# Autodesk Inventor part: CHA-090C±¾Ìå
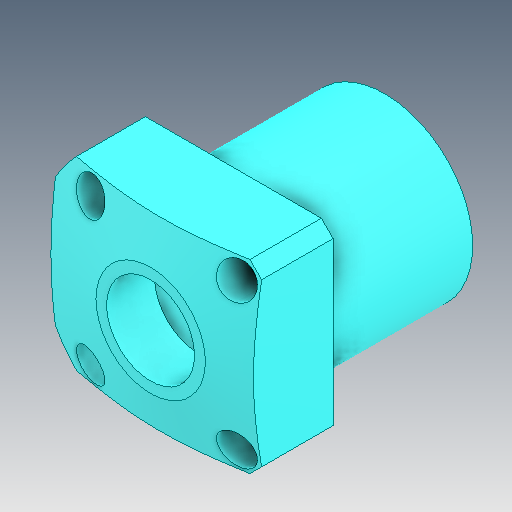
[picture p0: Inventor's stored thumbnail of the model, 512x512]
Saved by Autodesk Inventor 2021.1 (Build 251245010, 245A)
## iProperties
Created: 2021-05
Part Number: CHA-090C±¾Ìå
Material: Ogólny
Document SubType Name: Modeling
Designer: user
Density: 1 g/cm^3
Appearance: Domyślna
Author: user
Revision Number: ÈÎºÎ
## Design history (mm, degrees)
feature "ÊäÈë1"
node "Bryła1"
